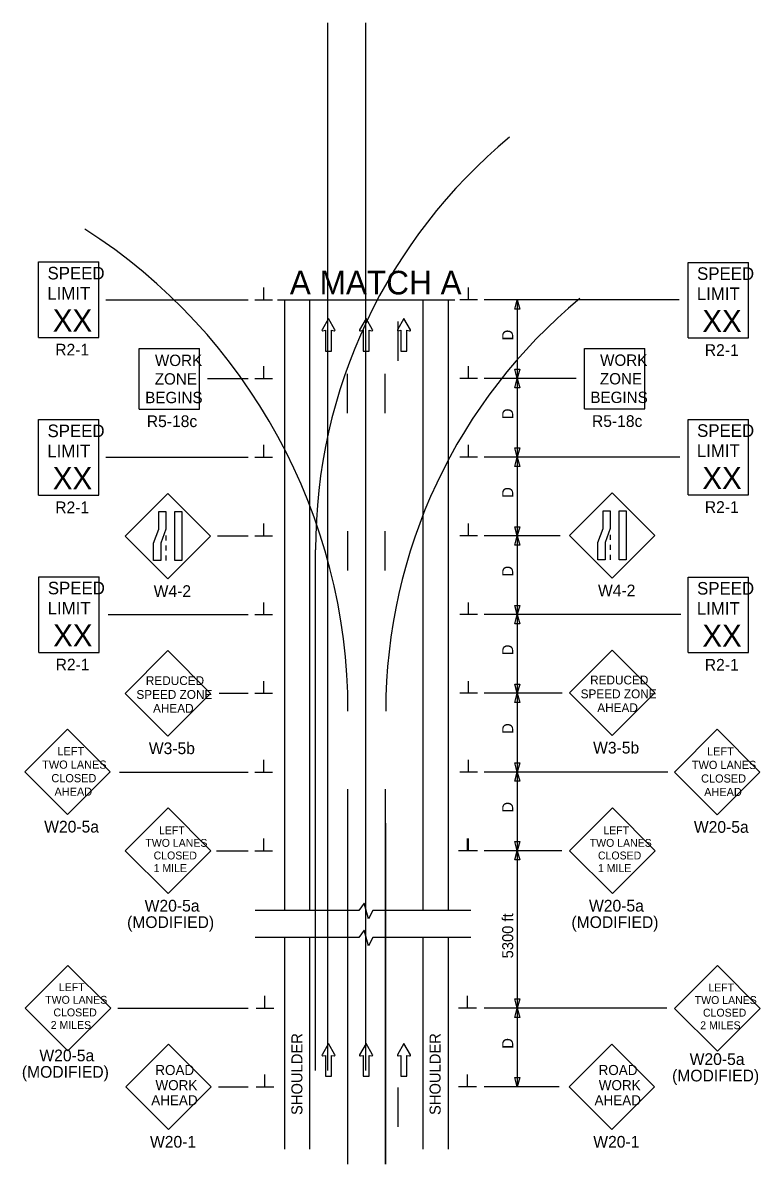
# Model space of a CAD drawing. Extents: x 16554 to 19508, y 5694 to 7079.
# Drawn here: x 17861 to 18330, y 6354 to 7079 of the extents above; entities that cross this region are included whole.
import ezdxf

# ---------------------------------------------------------------- set-up
doc = ezdxf.new("R2010")
doc.units = 0
for name, color, linetype in [('ALI_LEGAL_EX', 7, 'Continuous'), ('MT_SCRATCH_LEVEL_E', 7, 'Continuous'), ('PAVT_EDGE_EX', 7, 'Continuous'), ('TRAFFIC_SIGNS_PR', 7, 'Continuous'), ('TYPICAL_TEXT_DIMEN_PR', 7, 'Continuous')]:
    doc.layers.add(name, color=color, linetype=linetype)

msp = doc.modelspace()

# ---------------------------------------------------------------- linework, layer by layer
at = {"layer": 'ALI_LEGAL_EX'}
for p, q in [((18054.48, 7078.99), (18054.48, 6413.36)), ((18078.48, 7078.99), (18078.48, 6413.36)), ((18054.48, 6981.91), (18054.48, 6413.36)), ((18078.48, 6981.91), (18078.48, 6413.36)), ((18046.81, 6413.36), (18046.81, 6744.25)), ((18067.05, 6592.15), (18067.05, 6515)), ((18091.05, 6592.15), (18091.05, 6515)), ((18067.45, 6353.93), (18067.45, 6570.58)), ((18091.45, 6353.93), (18091.45, 6570.58)), ((18067.05, 6547.85), (18067.05, 6353.93)), ((18091.05, 6547.85), (18091.05, 6353.93))]:
    msp.add_line(p, q, dxfattribs=at)
for points in [[(18099.19, 6889.18), (18099.19, 6864.18)], [(18067.05, 6831.03), (18067.05, 6856.03)], [(18091.05, 6831.03), (18091.05, 6856.03)], [(18067.05, 6756.03), (18067.05, 6731.03)], [(18067.05, 6756.03), (18067.05, 6731.03)], [(18091.05, 6731.03), (18091.05, 6756.03)], [(18067.05, 6497.85), (18067.05, 6472.85)], [(18091.05, 6497.85), (18091.05, 6472.85)], [(18099.19, 6402.63), (18099.19, 6377.63)], [(18067.05, 6397.85), (18067.05, 6372.85)], [(18091.05, 6397.85), (18091.05, 6372.85)]]:
    msp.add_lwpolyline(points, dxfattribs=at)
for centre, radius, start, end in [((18386.81, 6744.25), 340, 129.56655, 180), ((17703.45, 6641.72), 364, 0, 57.29578), ((18431.45, 6641.72), 340, 129.56655, 180)]:
    msp.add_arc(centre, radius, start, end, dxfattribs=at)
at = {"layer": 'MT_SCRATCH_LEVEL_E'}
for p, q in [((18055.05, 6891.26), (18050.94, 6884.02)), ((18059.19, 6884.02), (18055.05, 6891.26)), ((18078.95, 6891.26), (18074.84, 6884.02)), ((18083.1, 6884.02), (18078.95, 6891.26)), ((18103, 6891.26), (18098.89, 6884.02)), ((18107.15, 6884.02), (18103, 6891.26)), ((18051.42, 6883.34), (18053.19, 6883.65)), ((18053.19, 6883.65), (18053.19, 6870.4)), ((18056.94, 6870.4), (18056.94, 6883.65)), ((18056.94, 6883.65), (18058.71, 6883.34)), ((18075.32, 6883.34), (18077.1, 6883.65)), ((18077.1, 6883.65), (18077.1, 6870.4)), ((18080.84, 6870.4), (18080.84, 6883.65)), ((18080.84, 6883.65), (18082.62, 6883.34)), ((18099.37, 6883.34), (18101.15, 6883.65)), ((18101.15, 6883.65), (18101.15, 6870.4)), ((18104.89, 6870.4), (18104.89, 6883.65)), ((18104.89, 6883.65), (18106.67, 6883.34)), ((18053.19, 6870.4), (18056.94, 6870.4)), ((18077.1, 6870.4), (18080.84, 6870.4)), ((18101.15, 6870.4), (18104.89, 6870.4)), ((18055.05, 6430.63), (18050.94, 6423.39)), ((18059.19, 6423.39), (18055.05, 6430.63)), ((18078.95, 6430.63), (18074.84, 6423.39)), ((18083.1, 6423.39), (18078.95, 6430.63)), ((18103, 6430.63), (18098.89, 6423.39)), ((18107.15, 6423.39), (18103, 6430.63)), ((18051.42, 6422.7), (18053.19, 6423.02)), ((18053.19, 6423.02), (18053.19, 6409.76)), ((18056.94, 6409.76), (18056.94, 6423.02)), ((18056.94, 6423.02), (18058.71, 6422.7)), ((18075.32, 6422.7), (18077.1, 6423.02)), ((18077.1, 6423.02), (18077.1, 6409.76)), ((18080.84, 6409.76), (18080.84, 6423.02)), ((18080.84, 6423.02), (18082.62, 6422.7)), ((18099.37, 6422.7), (18101.15, 6423.02)), ((18101.15, 6423.02), (18101.15, 6409.76)), ((18104.89, 6409.76), (18104.89, 6423.02)), ((18104.89, 6423.02), (18106.67, 6422.7)), ((18053.19, 6409.76), (18056.94, 6409.76)), ((18077.1, 6409.76), (18080.84, 6409.76)), ((18101.15, 6409.76), (18104.89, 6409.76))]:
    msp.add_line(p, q, dxfattribs=at)
for centre, start, end in [((18051.34, 6883.8), 150.42484, 279.96381), ((18058.78, 6883.8), 260.03619, 29.77312), ((18075.25, 6883.8), 150.42484, 279.96381), ((18082.69, 6883.8), 260.03619, 29.77312), ((18099.3, 6883.8), 150.42484, 279.96381), ((18106.74, 6883.8), 260.03619, 29.77312), ((18051.34, 6423.16), 150.42484, 279.96381), ((18058.78, 6423.16), 260.03619, 29.77312), ((18075.25, 6423.16), 150.42484, 279.96381), ((18082.69, 6423.16), 260.03619, 29.77312), ((18099.3, 6423.16), 150.42484, 279.96381), ((18106.74, 6423.16), 260.03619, 29.77312)]:
    msp.add_arc(centre, 0.463, start, end, dxfattribs=at)
at = {"layer": 'PAVT_EDGE_EX'}
for p, q in [((18027.05, 6903.04), (18027.05, 6545.99)), ((18043.05, 6903.04), (18043.05, 6545.99)), ((18115.05, 6903.04), (18115.05, 6545.99)), ((18131.05, 6903.04), (18131.05, 6545.99)), ((18027.05, 6553.04), (18027.05, 6515)), ((18043.05, 6553.04), (18043.05, 6515)), ((18115.05, 6553.04), (18115.05, 6515)), ((18131.05, 6553.04), (18131.05, 6515)), ((18027.05, 6497.85), (18027.05, 6363.46)), ((18043.05, 6497.85), (18043.05, 6363.46)), ((18115.05, 6497.85), (18115.05, 6363.46)), ((18131.05, 6497.85), (18131.05, 6363.46))]:
    msp.add_line(p, q, dxfattribs=at)
at = {"layer": 'TRAFFIC_SIGNS_PR'}
for p, q in [((17870.65, 6927.1), (17909.05, 6927.1)), ((17870.65, 6879.1), (17870.65, 6927.1)), ((17909.05, 6879.1), (17909.05, 6927.1)), ((18283.63, 6926.82), (18322.03, 6926.82)), ((18283.63, 6878.82), (18283.63, 6926.82)), ((18322.03, 6878.82), (18322.03, 6926.82)), ((17870.65, 6879.1), (17909.05, 6879.1)), ((18283.63, 6878.82), (18322.03, 6878.82)), ((17934.72, 6833.61), (17934.72, 6872.01)), ((17934.72, 6872.01), (17973.12, 6872.01)), ((17973.12, 6833.61), (17973.12, 6872.01)), ((18217.74, 6833.72), (18217.74, 6872.12)), ((18217.74, 6872.12), (18256.14, 6872.12)), ((18256.14, 6833.72), (18256.14, 6872.12)), ((17934.72, 6833.61), (17973.12, 6833.61)), ((18217.74, 6833.72), (18256.14, 6833.72)), ((17870.65, 6826.93), (17909.05, 6826.93)), ((17870.65, 6778.93), (17870.65, 6826.93)), ((17909.05, 6778.93), (17909.05, 6826.93)), ((18283.63, 6827.1), (18322.03, 6827.1)), ((18283.63, 6779.1), (18283.63, 6827.1)), ((18322.03, 6779.1), (18322.03, 6827.1)), ((17952.96, 6780), (17925.8, 6752.85)), ((17980.11, 6752.85), (17952.96, 6780)), ((18235.44, 6780.41), (18208.29, 6753.26)), ((18262.59, 6753.26), (18235.44, 6780.41)), ((17870.65, 6778.93), (17909.05, 6778.93)), ((18283.63, 6779.1), (18322.03, 6779.1)), ((17925.8, 6752.85), (17952.96, 6725.69)), ((17951.71, 6753.34), (17951.71, 6750.14)), ((17952.96, 6725.69), (17980.11, 6752.85)), ((18208.29, 6753.26), (18235.44, 6726.1)), ((18234.19, 6753.75), (18234.19, 6750.55)), ((18235.44, 6726.1), (18262.59, 6753.26)), ((17951.71, 6746.94), (17951.71, 6743.74)), ((18234.19, 6747.35), (18234.19, 6744.15)), ((17951.71, 6740.54), (17951.71, 6737.34)), ((18234.19, 6740.95), (18234.19, 6737.75)), ((17870.87, 6727.06), (17909.27, 6727.06)), ((17870.87, 6679.06), (17870.87, 6727.06)), ((17909.27, 6679.06), (17909.27, 6727.06)), ((18283.63, 6726.9), (18322.03, 6726.9)), ((18283.63, 6678.9), (18283.63, 6726.9)), ((18322.03, 6678.9), (18322.03, 6726.9)), ((17870.87, 6679.06), (17909.27, 6679.06)), ((17952.88, 6680.16), (17925.73, 6653)), ((17980.04, 6653), (17952.88, 6680.16)), ((18235.33, 6680.54), (18208.18, 6653.39)), ((18262.48, 6653.39), (18235.33, 6680.54)), ((18283.63, 6678.9), (18322.03, 6678.9)), ((17925.73, 6653), (17952.88, 6625.85)), ((17952.88, 6625.85), (17980.04, 6653)), ((18208.18, 6653.39), (18235.33, 6626.23)), ((18235.33, 6626.23), (18262.48, 6653.39)), ((17889.17, 6630.36), (17862.02, 6603.21)), ((17916.32, 6603.21), (17889.17, 6630.36)), ((18302.22, 6630.17), (18275.07, 6603.02)), ((18329.38, 6603.02), (18302.22, 6630.17)), ((17862.02, 6603.21), (17889.17, 6576.06)), ((17889.17, 6576.06), (17916.32, 6603.21)), ((18275.07, 6603.02), (18302.22, 6575.87)), ((18302.22, 6575.87), (18329.38, 6603.02)), ((17953.05, 6580.23), (17925.86, 6553.05)), ((17980.23, 6553.05), (17953.05, 6580.23)), ((18235.55, 6580.23), (18208.36, 6553.05)), ((18262.74, 6553.05), (18235.55, 6580.23)), ((17925.86, 6553.05), (17953.05, 6525.86)), ((17953.05, 6525.86), (17980.23, 6553.05)), ((18208.36, 6553.05), (18235.55, 6525.86)), ((18235.55, 6525.86), (18262.74, 6553.05)), ((17889.38, 6480.23), (17862.19, 6453.05)), ((17916.57, 6453.05), (17889.38, 6480.23)), ((18302.33, 6480.08), (18275.14, 6452.89)), ((18329.52, 6452.89), (18302.33, 6480.08)), ((17862.19, 6453.05), (17889.38, 6425.86)), ((17889.38, 6425.86), (17916.57, 6453.05)), ((18275.14, 6452.89), (18302.33, 6425.7)), ((18302.33, 6425.7), (18329.52, 6452.89)), ((17953.4, 6430.16), (17926.25, 6403.01)), ((17980.55, 6403.01), (17953.4, 6430.16)), ((18235.23, 6430.16), (18208.08, 6403.01)), ((18262.38, 6403.01), (18235.23, 6430.16)), ((17926.25, 6403.01), (17953.4, 6375.86)), ((17953.4, 6375.86), (17980.55, 6403.01)), ((18208.08, 6403.01), (18235.23, 6375.86)), ((18235.23, 6375.86), (18262.38, 6403.01))]:
    msp.add_line(p, q, dxfattribs=at)
for points in [[(17951.71, 6768.58), (17951.71, 6757.4), (17948.37, 6748.52), (17948.37, 6737.34), (17943.87, 6737.34), (17943.87, 6748.52), (17947.22, 6757.4), (17947.22, 6768.58)], [(17961.85, 6768.58), (17961.85, 6737.34), (17957.35, 6737.34), (17957.35, 6768.58)], [(18234.19, 6768.99), (18234.19, 6757.81), (18230.85, 6748.93), (18230.85, 6737.75), (18226.36, 6737.75), (18226.36, 6748.93), (18229.7, 6757.81), (18229.7, 6768.99)], [(18244.33, 6768.99), (18244.33, 6737.75), (18239.84, 6737.75), (18239.84, 6768.99)]]:
    msp.add_lwpolyline(points, close=True, dxfattribs=at)
at = {"layer": 'TYPICAL_TEXT_DIMEN_PR'}
for p, q in [((18013.92, 6903.04), (18013.92, 6910.83)), ((18144.17, 6903.04), (18144.17, 6910.83)), ((17913.52, 6903.04), (18004.05, 6903.04)), ((18008.3, 6903.04), (18019.55, 6903.04)), ((18022.72, 6903.04), (18135.37, 6903.04)), ((18149.8, 6903.04), (18138.55, 6903.04)), ((18277.95, 6903.04), (18154.05, 6903.04)), ((18173.48, 6897.18), (18175.05, 6903.04)), ((18175.05, 6903.04), (18175.05, 6853.04)), ((18175.05, 6903.04), (18176.62, 6897.18)), ((18175.05, 6897.18), (18173.48, 6897.18)), ((18176.62, 6897.18), (18175.05, 6897.18)), ((18013.92, 6853.04), (18013.92, 6860.83)), ((18144.17, 6853.04), (18144.17, 6860.83)), ((17978.05, 6853.04), (18004.05, 6853.04)), ((18008.3, 6853.04), (18019.55, 6853.04)), ((18149.8, 6853.04), (18138.55, 6853.04)), ((18212.51, 6853.04), (18154.05, 6853.04)), ((18175.05, 6853.04), (18173.48, 6858.91)), ((18173.48, 6858.91), (18175.05, 6858.91)), ((18173.48, 6847.18), (18175.05, 6853.04)), ((18175.05, 6858.91), (18176.62, 6858.91)), ((18176.62, 6858.91), (18175.05, 6853.04)), ((18175.05, 6853.04), (18175.05, 6803.04)), ((18175.05, 6853.04), (18176.62, 6847.18)), ((18175.05, 6847.18), (18173.48, 6847.18)), ((18176.62, 6847.18), (18175.05, 6847.18)), ((18013.92, 6803.04), (18013.92, 6810.83)), ((18144.17, 6803.04), (18144.17, 6810.83)), ((18175.05, 6803.04), (18173.48, 6808.91)), ((18173.48, 6808.91), (18175.05, 6808.91)), ((18175.05, 6808.91), (18176.62, 6808.91)), ((18176.62, 6808.91), (18175.05, 6803.04)), ((17913.52, 6803.04), (18004.05, 6803.04)), ((18008.3, 6803.04), (18019.55, 6803.04)), ((18149.8, 6803.04), (18138.55, 6803.04)), ((18278.53, 6803.04), (18154.05, 6803.04)), ((18173.48, 6797.18), (18175.05, 6803.04)), ((18175.05, 6803.04), (18175.05, 6753.04)), ((18175.05, 6803.04), (18176.62, 6797.18)), ((18175.05, 6797.18), (18173.48, 6797.18)), ((18176.62, 6797.18), (18175.05, 6797.18)), ((18013.92, 6753.04), (18013.92, 6760.83)), ((18144.17, 6753.04), (18144.17, 6760.83)), ((18175.05, 6753.04), (18173.48, 6758.91)), ((18173.48, 6758.91), (18175.05, 6758.91)), ((18175.05, 6758.91), (18176.62, 6758.91)), ((18176.62, 6758.91), (18175.05, 6753.04)), ((17984.47, 6753.04), (18004.05, 6753.04)), ((18008.3, 6753.04), (18019.55, 6753.04)), ((18149.8, 6753.04), (18138.55, 6753.04)), ((18202.43, 6753.04), (18154.05, 6753.04)), ((18173.48, 6747.18), (18175.05, 6753.04)), ((18175.05, 6753.04), (18175.05, 6703.04)), ((18175.05, 6753.04), (18176.62, 6747.18)), ((18175.05, 6747.18), (18173.48, 6747.18)), ((18176.62, 6747.18), (18175.05, 6747.18)), ((18013.92, 6703.04), (18013.92, 6710.83)), ((18144.17, 6703.04), (18144.17, 6710.83)), ((18175.05, 6703.04), (18173.48, 6708.91)), ((18173.48, 6708.91), (18175.05, 6708.91)), ((18175.05, 6708.91), (18176.62, 6708.91)), ((18176.62, 6708.91), (18175.05, 6703.04)), ((17915.08, 6703.04), (18004.05, 6703.04)), ((18008.3, 6703.04), (18019.55, 6703.04)), ((18149.8, 6703.04), (18138.55, 6703.04)), ((18279.1, 6703.04), (18154.05, 6703.04)), ((18173.48, 6697.18), (18175.05, 6703.04)), ((18175.05, 6703.04), (18175.05, 6653.04)), ((18175.05, 6703.04), (18176.62, 6697.18)), ((18175.05, 6697.18), (18173.48, 6697.18)), ((18176.62, 6697.18), (18175.05, 6697.18)), ((18013.92, 6653.04), (18013.92, 6660.83)), ((18144.17, 6653.04), (18144.17, 6660.83)), ((18175.05, 6653.04), (18173.48, 6658.91)), ((18173.48, 6658.91), (18175.05, 6658.91)), ((18175.05, 6658.91), (18176.62, 6658.91)), ((18176.62, 6658.91), (18175.05, 6653.04)), ((17985.65, 6653.04), (18004.05, 6653.04)), ((18008.3, 6653.04), (18019.55, 6653.04)), ((18149.8, 6653.04), (18138.55, 6653.04)), ((18203.64, 6653.04), (18154.05, 6653.04)), ((18173.48, 6647.18), (18175.05, 6653.04)), ((18175.05, 6653.04), (18175.05, 6603.04)), ((18175.05, 6653.04), (18176.62, 6647.18)), ((18175.05, 6647.18), (18173.48, 6647.18)), ((18176.62, 6647.18), (18175.05, 6647.18)), ((18013.92, 6603.04), (18013.92, 6610.83)), ((18144.17, 6603.04), (18144.17, 6610.83)), ((18175.05, 6603.04), (18173.48, 6608.91)), ((18173.48, 6608.91), (18175.05, 6608.91)), ((18175.05, 6608.91), (18176.62, 6608.91)), ((18176.62, 6608.91), (18175.05, 6603.04)), ((17922.15, 6603.04), (18004.05, 6603.04)), ((18008.3, 6603.04), (18019.55, 6603.04)), ((18149.8, 6603.04), (18138.55, 6603.04)), ((18270.73, 6603.04), (18154.05, 6603.04)), ((18173.48, 6597.18), (18175.05, 6603.04)), ((18175.05, 6603.04), (18175.05, 6553.04)), ((18175.05, 6603.04), (18176.62, 6597.18)), ((18175.05, 6597.18), (18173.48, 6597.18)), ((18176.62, 6597.18), (18175.05, 6597.18)), ((18013.92, 6553.04), (18013.92, 6560.83)), ((18143.42, 6553.04), (18143.42, 6560.83)), ((18144.17, 6553.04), (18144.17, 6560.83)), ((18175.05, 6553.04), (18173.48, 6558.91)), ((18173.48, 6558.91), (18175.05, 6558.91)), ((18175.05, 6558.91), (18176.62, 6558.91)), ((18176.62, 6558.91), (18175.05, 6553.04)), ((17983.75, 6553.04), (18004.05, 6553.04)), ((18008.3, 6553.04), (18019.55, 6553.04)), ((18149.05, 6553.04), (18137.8, 6553.04)), ((18149.8, 6553.04), (18138.55, 6553.04)), ((18203.4, 6553.04), (18154.05, 6553.04)), ((18173.48, 6547.18), (18175.05, 6553.04)), ((18175.05, 6553.04), (18175.05, 6453.04)), ((18175.05, 6553.04), (18176.62, 6547.18)), ((18175.05, 6547.18), (18173.48, 6547.18)), ((18176.62, 6547.18), (18175.05, 6547.18)), ((18077.65, 6519.78), (18074.4, 6514.98)), ((18080.39, 6509.84), (18077.65, 6519.78)), ((18074.4, 6514.98), (18008.45, 6514.98)), ((18083.14, 6514.98), (18080.39, 6509.84)), ((18145.47, 6514.98), (18083.14, 6514.98)), ((18074.4, 6497.85), (18008.45, 6497.85)), ((18077.65, 6502.65), (18074.4, 6497.85)), ((18080.39, 6492.71), (18077.65, 6502.65)), ((18083.14, 6497.85), (18080.39, 6492.71)), ((18145.47, 6497.85), (18083.14, 6497.85)), ((18014.67, 6453.04), (18014.67, 6460.83)), ((18143.42, 6453.04), (18143.42, 6460.83)), ((18175.05, 6453.04), (18173.48, 6458.91)), ((18173.48, 6458.91), (18175.05, 6458.91)), ((18175.05, 6458.91), (18176.62, 6458.91)), ((18176.62, 6458.91), (18175.05, 6453.04)), ((17921.07, 6453.04), (18004.05, 6453.04)), ((18009.05, 6453.04), (18020.3, 6453.04)), ((18149.05, 6453.04), (18137.8, 6453.04)), ((18270.17, 6453.04), (18154.05, 6453.04)), ((18173.48, 6447.18), (18175.05, 6453.04)), ((18175.05, 6447.18), (18173.48, 6447.18)), ((18175.05, 6453.04), (18175.05, 6403.04)), ((18175.05, 6453.04), (18176.62, 6447.18)), ((18176.62, 6447.18), (18175.05, 6447.18)), ((18014.67, 6403.04), (18014.67, 6410.83)), ((18143.42, 6403.04), (18143.42, 6410.83)), ((17985.05, 6403.04), (18004.05, 6403.04)), ((18009.05, 6403.04), (18020.3, 6403.04)), ((18149.05, 6403.04), (18137.8, 6403.04)), ((18201.69, 6403.04), (18154.05, 6403.04)), ((18175.05, 6403.04), (18173.48, 6408.91)), ((18173.48, 6408.91), (18175.05, 6408.91)), ((18175.05, 6408.91), (18176.62, 6408.91)), ((18176.62, 6408.91), (18175.05, 6403.04))]:
    msp.add_line(p, q, dxfattribs=at)

# ---------------------------------------------------------------- texts
at = {"layer": 'TRAFFIC_SIGNS_PR'}
for s, height, p in [('SPEED', 8, (17876.42, 6915.97)), ('SPEED', 8, (18289.39, 6915.68)), ('LIMIT', 8, (17876.26, 6903.17)), ('LIMIT', 8, (18289.23, 6902.88)), ('XX', 14.031, (17879.77, 6882.86)), ('XX', 14.031, (18292.74, 6882.58)), ('R2-1', 7.44, (17881.33, 6867.67)), ('R2-1', 7.44, (18294.3, 6867.38)), ('WORK', 7.217, (17944.72, 6860.98)), ('WORK', 7.217, (18227.74, 6861.09)), ('ZONE', 7.217, (17944.6, 6849.17)), ('ZONE', 7.217, (18227.62, 6849.28)), ('BEGINS', 7.217, (17938.53, 6837.36)), ('BEGINS', 7.217, (18221.55, 6837.47)), ('SPEED', 8, (17876.42, 6815.79)), ('R5-18c', 7.44, (17939.53, 6822.17)), ('R5-18c', 7.44, (18222.55, 6822.28)), ('SPEED', 8, (18289.4, 6815.96)), ('LIMIT', 8, (17876.26, 6802.99)), ('LIMIT', 8, (18289.23, 6803.16)), ('XX', 14.031, (17879.77, 6782.69)), ('XX', 14.031, (18292.74, 6782.85)), ('R2-1', 7.44, (17881.33, 6767.49)), ('R2-1', 7.44, (18294.31, 6767.66)), ('SPEED', 8, (17876.64, 6715.92)), ('W4-2', 7.44, (17943.91, 6714.26)), ('W4-2', 7.44, (18226.4, 6714.66)), ('SPEED', 8, (18289.39, 6715.76)), ('LIMIT', 8, (17876.48, 6703.12)), ('LIMIT', 8, (18289.23, 6702.96)), ('XX', 14.031, (17879.99, 6682.82)), ('XX', 14.031, (18292.74, 6682.65)), ('R2-1', 7.44, (17881.55, 6667.62)), ('R2-1', 7.44, (18294.3, 6667.46)), ('REDUCED', 5.6, (17938.94, 6658.31)), ('REDUCED', 5.6, (18221.39, 6658.69)), ('SPEED ZONE', 5.6, (17932.93, 6649.51)), ('SPEED ZONE', 5.6, (18215.38, 6649.9)), ('AHEAD', 5.6, (17943.49, 6640.71)), ('AHEAD', 5.6, (18225.94, 6641.1)), ('W3-5b', 7.44, (17940.84, 6614.41)), ('W3-5b', 7.44, (18223.29, 6614.79)), ('LEFT', 5.2, (17882.71, 6613.75)), ('LEFT', 5.2, (18295.76, 6613.56)), ('TWO LANES', 5.2, (17873.03, 6605.15)), ('TWO LANES', 5.2, (18286.09, 6604.96)), ('CLOSED', 5.2, (17878.88, 6596.55)), ('CLOSED', 5.2, (18291.94, 6596.36)), ('AHEAD', 5.2, (17880.83, 6587.95)), ('AHEAD', 5.2, (18293.88, 6587.76)), ('W20-5a', 7.44, (17874.31, 6564.62)), ('W20-5a', 7.44, (18287.37, 6564.44)), ('LEFT', 5.006, (17947.29, 6563.54)), ('LEFT', 5.006, (18229.79, 6563.54)), ('TWO LANES', 5.006, (17938.64, 6555.53)), ('TWO LANES', 5.006, (18221.14, 6555.53)), ('CLOSED', 5.006, (17943.87, 6547.52)), ('CLOSED', 5.006, (18226.37, 6547.52)), ('1 MILE', 5.006, (17943.86, 6539.51)), ('1 MILE', 5.006, (18226.37, 6539.51)), ('W20-5a', 7.449, (17938.17, 6514.4)), ('W20-5a', 7.449, (18220.67, 6514.41)), ('(MODIFIED)', 7.449, (17927.01, 6503.95)), ('(MODIFIED)', 7.449, (18209.51, 6503.95)), ('LEFT', 5.006, (17883.62, 6463.84)), ('LEFT', 5.006, (18296.57, 6463.69)), ('TWO LANES', 5.006, (17874.97, 6455.83)), ('TWO LANES', 5.006, (18287.92, 6455.68)), ('CLOSED', 5.006, (17880.2, 6447.82)), ('CLOSED', 5.006, (18293.15, 6447.67)), ('2 MILES', 5.006, (17878.45, 6439.82)), ('2 MILES', 5.006, (18291.4, 6439.66)), ('W20-5a', 7.449, (17871.25, 6419.28)), ('W20-5a', 7.449, (18284.67, 6416.94)), ('ROAD', 6.4, (17944.94, 6410.55)), ('ROAD', 6.4, (18226.77, 6410.55)), ('(MODIFIED)', 7.449, (17860.09, 6408.83)), ('(MODIFIED)', 7.449, (18273.51, 6406.49)), ('WORK', 6.4, (17945.05, 6400.94)), ('WORK', 6.4, (18226.88, 6400.94)), ('AHEAD', 6.4, (17942.36, 6391.35)), ('AHEAD', 6.4, (18224.19, 6391.35)), ('W20-1', 7.44, (17941.57, 6364.42)), ('W20-1', 7.44, (18223.4, 6364.42))]:
    msp.add_text(s, height=height, dxfattribs=at).set_placement(p)
at = {"layer": 'TYPICAL_TEXT_DIMEN_PR'}
msp.add_text('A MATCH A', height=15, dxfattribs=at).set_placement((18030.46, 6906.45))
for s, p in [('D', (18172.49, 6877.26)), ('D', (18172.49, 6827.26)), ('D', (18172.49, 6777.26)), ('D', (18172.49, 6727.26)), ('D', (18172.49, 6677.26)), ('D', (18172.49, 6627.26)), ('D', (18172.49, 6577.26)), ('5300 ft', (18172.49, 6484.65)), ('SHOULDER', (18038.47, 6385.17)), ('SHOULDER', (18126.33, 6385.17)), ('D', (18172.49, 6427.26))]:
    msp.add_text(s, height=7, rotation=90, dxfattribs=at).set_placement(p)

doc.saveas('drawing.dxf')
